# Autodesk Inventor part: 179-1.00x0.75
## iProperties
Created: 2007-06
Part Number: 179-1.00x0.75
Document SubType Name: Modeling
Designer: btaylor
Density: 1 g/cm^3
Author: btaylor
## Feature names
1. Extrusion1
2. Extrusion3
3. Extrusion15
4. Fillet11
5. Fillet12
6. Extrusion16
7. Extrusion17
8. Extrusion18
9. Fillet13
10. Fillet16
11. Chamfer5
12. Chamfer6
13. Fillet14
